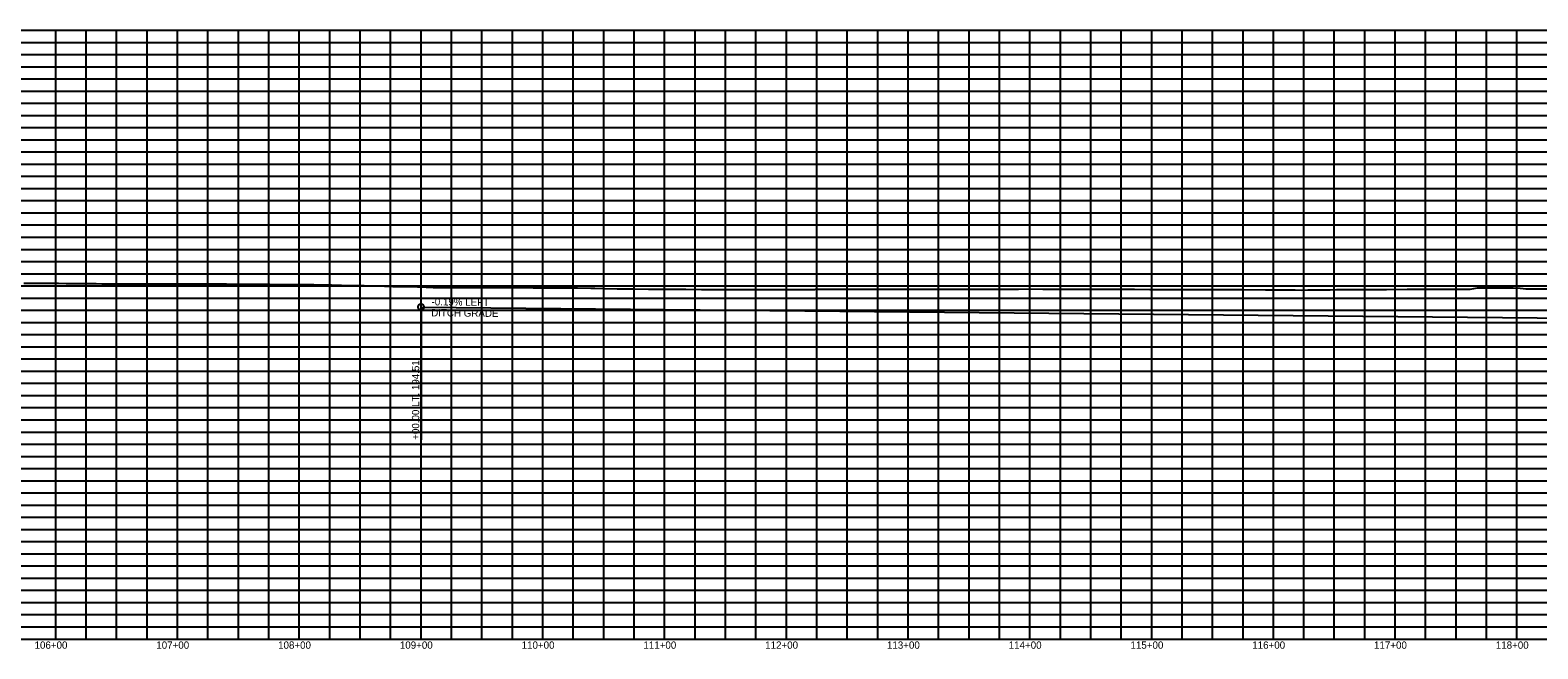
# Model space of a CAD drawing. Extents: x 1399671 to 1408349, y 1930471 to 1933387.
# Drawn here: x 1400903 to 1402141, y 1932871 to 1933379 of the extents above; entities that cross this region are included whole.
import ezdxf

# ---------------------------------------------------------------- set-up
doc = ezdxf.new("R2010")
doc.units = 0
for name, color, linetype in [('R_Exist Surface', 7, 'Continuous'), ('R_Grid', 7, 'Continuous'), ('R_Grid Annot', 7, 'Continuous'), ('R_Vert Alg', 7, 'Continuous'), ('R_Vert Alg Annot', 7, 'Continuous')]:
    doc.layers.add(name, color=color, linetype=linetype)

msp = doc.modelspace()

# ---------------------------------------------------------------- linework, layer by layer
at = {"layer": 'R_Exist Surface'}
msp.add_lwpolyline([(1400897.9, 1933170.9), (1400905.4, 1933170.8), (1400912.1, 1933170.8), (1400918.2, 1933170.7), (1400919.1, 1933170.7), (1400926.4, 1933170.7), (1400932.8, 1933170.6), (1400940.1, 1933170.6), (1400947.4, 1933170.5), (1400957.3, 1933170.5), (1400962, 1933170.4), (1400974.2, 1933170.3), (1400981.9, 1933170.3), (1400983.9, 1933170.3), (1401000.9, 1933170.3), (1401005.8, 1933170.3), (1401006.3, 1933170.3), (1401027.6, 1933170.3), (1401027.6, 1933170.3), (1401030.7, 1933170.3), (1401042.9, 1933170.2), (1401043.8, 1933170.2), (1401049.5, 1933170.2), (1401056.6, 1933170.2), (1401057, 1933170.2), (1401064.4, 1933170.2), (1401070.1, 1933170.1), (1401070.8, 1933170.1), (1401071.2, 1933170.1), (1401083.2, 1933169.9), (1401085.4, 1933169.9), (1401092.8, 1933169.9), (1401096.3, 1933169.9), (1401100.1, 1933169.9), (1401109.5, 1933169.8), (1401114.5, 1933169.8), (1401114.7, 1933169.8), (1401122.6, 1933169.8), (1401129.3, 1933169.8), (1401135.8, 1933169.7), (1401136.1, 1933169.7), (1401150.7, 1933169.4), (1401157.8, 1933169.2), (1401159, 1933169.2), (1401177.6, 1933168.8), (1401179.4, 1933168.7), (1401182.3, 1933168.7), (1401194.3, 1933168.4), (1401195.3, 1933168.4), (1401201, 1933168.2), (1401205.4, 1933168.2), (1401208.4, 1933168.1), (1401208.4, 1933168.1), (1401221.3, 1933167.8), (1401221.6, 1933167.7), (1401222.7, 1933167.7), (1401234.2, 1933167.4), (1401234.7, 1933167.4), (1401244.3, 1933167.4), (1401247.3, 1933167.4), (1401248, 1933167.4), (1401260.5, 1933167.3), (1401261.3, 1933167.3), (1401262.1, 1933167.3), (1401266, 1933167.3), (1401274.5, 1933167.3), (1401275.5, 1933167.3), (1401287.6, 1933167.2), (1401287.8, 1933167.2), (1401289, 1933167.2), (1401301.4, 1933167.2), (1401302.7, 1933167.2), (1401309.3, 1933167.2), (1401314.9, 1933167.2), (1401316.4, 1933167.1), (1401328.5, 1933167.1), (1401330.1, 1933167.1), (1401330.9, 1933167.1), (1401342, 1933167.1), (1401344.9, 1933167.1), (1401352.6, 1933166.9), (1401363.6, 1933166.7), (1401366.8, 1933166.7), (1401374.2, 1933166.5), (1401385.3, 1933166.3), (1401395.8, 1933166.2), (1401397.1, 1933166.2), (1401399.4, 1933166.2), (1401411.1, 1933166), (1401413.5, 1933166), (1401417.5, 1933166), (1401425.1, 1933165.9), (1401427.6, 1933165.9), (1401439.1, 1933165.8), (1401439.1, 1933165.8), (1401441.7, 1933165.8), (1401454.4, 1933165.7), (1401457.3, 1933165.7), (1401460.8, 1933165.7), (1401470, 1933165.6), (1401472.9, 1933165.6), (1401475.8, 1933165.7), (1401482.4, 1933165.6), (1401488.5, 1933165.6), (1401491.4, 1933165.6), (1401504.1, 1933165.5), (1401504.1, 1933165.5), (1401506.8, 1933165.6), (1401517.7, 1933165.6), (1401520.5, 1933165.6), (1401525.7, 1933165.6), (1401531.4, 1933165.6), (1401534.3, 1933165.7), (1401545.1, 1933165.7), (1401547.4, 1933165.7), (1401548, 1933165.8), (1401558.8, 1933165.8), (1401562, 1933165.8), (1401569, 1933165.8), (1401573.2, 1933165.8), (1401576.5, 1933165.8), (1401587.7, 1933165.9), (1401590.6, 1933165.9), (1401598.8, 1933166), (1401602.1, 1933166), (1401613.1, 1933166), (1401616.5, 1933166), (1401627.6, 1933166), (1401630.7, 1933166), (1401641.9, 1933166), (1401645, 1933166), (1401656.1, 1933166), (1401659.2, 1933165.9), (1401670.4, 1933165.9), (1401673.4, 1933165.9), (1401676.3, 1933165.9), (1401686.2, 1933165.9), (1401689.1, 1933166), (1401699, 1933166), (1401702, 1933166), (1401711.8, 1933166), (1401714.9, 1933166), (1401724.7, 1933166.1), (1401734.8, 1933166), (1401738, 1933166), (1401748.2, 1933166), (1401751.4, 1933166), (1401761.5, 1933166), (1401764.7, 1933166), (1401774.9, 1933165.9), (1401778.1, 1933165.9), (1401790.5, 1933165.9), (1401794.1, 1933165.9), (1401806.5, 1933165.8), (1401810.1, 1933165.8), (1401822.6, 1933165.7), (1401826.1, 1933165.7), (1401829.6, 1933165.7), (1401842.2, 1933165.6), (1401845.3, 1933165.6), (1401856.3, 1933165.6), (1401859.5, 1933165.6), (1401870.5, 1933165.6), (1401873.6, 1933165.5), (1401884.6, 1933165.5), (1401895.6, 1933165.5), (1401898.8, 1933165.5), (1401917.7, 1933165.4), (1401923, 1933165.4), (1401941.9, 1933165.3), (1401947.2, 1933165.2), (1401952.4, 1933165.4), (1401970.9, 1933165.4), (1401976.1, 1933165.5), (1401994.7, 1933165.6), (1401997.4, 1933165.5), (1402014.3, 1933165.7), (1402017.1, 1933165.7), (1402034.1, 1933165.9), (1402036.8, 1933165.8), (1402039.4, 1933165.8), (1402052.7, 1933165.9), (1402056.8, 1933165.8), (1402070.4, 1933165.9), (1402076.9, 1933165.9), (1402085.8, 1933166), (1402091.7, 1933167.1), (1402104.4, 1933167.1), (1402121.1, 1933167.1), (1402126.8, 1933166.8), (1402129.2, 1933166.5), (1402131.6, 1933166.2), (1402150.7, 1933166.1)], dxfattribs=at)
at = {"layer": 'R_Grid'}
for p, q in [((1400324.2, 1933378.6), (1408224.2, 1933378.6)), ((1400324.2, 1933378.6), (1408224.2, 1933378.6)), ((1400324.2, 1933368.6), (1408224.2, 1933368.6)), ((1400924.2, 1932878.6), (1400924.2, 1933378.6)), ((1400949.2, 1932878.6), (1400949.2, 1933378.6)), ((1400974.2, 1932878.6), (1400974.2, 1933378.6)), ((1400999.2, 1932878.6), (1400999.2, 1933378.6)), ((1401024.2, 1932878.6), (1401024.2, 1933378.6)), ((1401049.2, 1932878.6), (1401049.2, 1933378.6)), ((1401074.2, 1932878.6), (1401074.2, 1933378.6)), ((1401099.2, 1932878.6), (1401099.2, 1933378.6)), ((1401124.2, 1932878.6), (1401124.2, 1933378.6)), ((1401149.2, 1932878.6), (1401149.2, 1933378.6)), ((1401174.2, 1932878.6), (1401174.2, 1933378.6)), ((1401199.2, 1932878.6), (1401199.2, 1933378.6)), ((1401224.2, 1932878.6), (1401224.2, 1933378.6)), ((1401249.2, 1932878.6), (1401249.2, 1933378.6)), ((1401274.2, 1932878.6), (1401274.2, 1933378.6)), ((1401299.2, 1932878.6), (1401299.2, 1933378.6)), ((1401324.2, 1932878.6), (1401324.2, 1933378.6)), ((1401349.2, 1932878.6), (1401349.2, 1933378.6)), ((1401374.2, 1932878.6), (1401374.2, 1933378.6)), ((1401399.2, 1932878.6), (1401399.2, 1933378.6)), ((1401424.2, 1932878.6), (1401424.2, 1933378.6)), ((1401449.2, 1932878.6), (1401449.2, 1933378.6)), ((1401474.2, 1932878.6), (1401474.2, 1933378.6)), ((1401499.2, 1932878.6), (1401499.2, 1933378.6)), ((1401524.2, 1932878.6), (1401524.2, 1933378.6)), ((1401549.2, 1932878.6), (1401549.2, 1933378.6)), ((1401574.2, 1932878.6), (1401574.2, 1933378.6)), ((1401599.2, 1932878.6), (1401599.2, 1933378.6)), ((1401624.2, 1932878.6), (1401624.2, 1933378.6)), ((1401649.2, 1932878.6), (1401649.2, 1933378.6)), ((1401674.2, 1932878.6), (1401674.2, 1933378.6)), ((1401699.2, 1932878.6), (1401699.2, 1933378.6)), ((1401724.2, 1932878.6), (1401724.2, 1933378.6)), ((1401749.2, 1932878.6), (1401749.2, 1933378.6)), ((1401774.2, 1932878.6), (1401774.2, 1933378.6)), ((1401799.2, 1932878.6), (1401799.2, 1933378.6)), ((1401824.2, 1932878.6), (1401824.2, 1933378.6)), ((1401849.2, 1932878.6), (1401849.2, 1933378.6)), ((1401874.2, 1932878.6), (1401874.2, 1933378.6)), ((1401899.2, 1932878.6), (1401899.2, 1933378.6)), ((1401924.2, 1932878.6), (1401924.2, 1933378.6)), ((1401949.2, 1932878.6), (1401949.2, 1933378.6)), ((1401974.2, 1932878.6), (1401974.2, 1933378.6)), ((1401999.2, 1932878.6), (1401999.2, 1933378.6)), ((1402024.2, 1932878.6), (1402024.2, 1933378.6)), ((1402049.2, 1932878.6), (1402049.2, 1933378.6)), ((1402074.2, 1932878.6), (1402074.2, 1933378.6)), ((1402099.2, 1932878.6), (1402099.2, 1933378.6)), ((1402124.2, 1932878.6), (1402124.2, 1933378.6)), ((1400324.2, 1933358.6), (1408224.2, 1933358.6)), ((1400324.2, 1933348.6), (1408224.2, 1933348.6)), ((1400324.2, 1933338.6), (1408224.2, 1933338.6)), ((1400324.2, 1933328.6), (1408224.2, 1933328.6)), ((1400324.2, 1933318.6), (1408224.2, 1933318.6)), ((1400324.2, 1933308.6), (1408224.2, 1933308.6)), ((1400324.2, 1933298.6), (1408224.2, 1933298.6)), ((1400324.2, 1933288.6), (1408224.2, 1933288.6)), ((1400324.2, 1933278.6), (1408224.2, 1933278.6)), ((1400324.2, 1933268.6), (1408224.2, 1933268.6)), ((1400324.2, 1933258.6), (1408224.2, 1933258.6)), ((1400324.2, 1933248.6), (1408224.2, 1933248.6)), ((1400324.2, 1933238.6), (1408224.2, 1933238.6)), ((1400324.2, 1933228.6), (1408224.2, 1933228.6)), ((1400324.2, 1933218.6), (1408224.2, 1933218.6)), ((1400324.2, 1933208.6), (1408224.2, 1933208.6)), ((1400324.2, 1933198.6), (1408224.2, 1933198.6)), ((1400324.2, 1933188.6), (1408224.2, 1933188.6)), ((1400324.2, 1933178.6), (1408224.2, 1933178.6)), ((1400324.2, 1933168.6), (1408224.2, 1933168.6)), ((1400324.2, 1933158.6), (1408224.2, 1933158.6)), ((1400324.2, 1933148.6), (1408224.2, 1933148.6)), ((1400324.2, 1933138.6), (1408224.2, 1933138.6)), ((1400324.2, 1933128.6), (1408224.2, 1933128.6)), ((1400324.2, 1933118.6), (1408224.2, 1933118.6)), ((1400324.2, 1933108.6), (1408224.2, 1933108.6)), ((1400324.2, 1933098.6), (1408224.2, 1933098.6)), ((1400324.2, 1933088.6), (1408224.2, 1933088.6)), ((1400324.2, 1933078.6), (1408224.2, 1933078.6)), ((1400324.2, 1933068.6), (1408224.2, 1933068.6)), ((1400324.2, 1933058.6), (1408224.2, 1933058.6)), ((1400324.2, 1933048.6), (1408224.2, 1933048.6)), ((1400324.2, 1933038.6), (1408224.2, 1933038.6)), ((1400324.2, 1933028.6), (1408224.2, 1933028.6)), ((1400324.2, 1933018.6), (1408224.2, 1933018.6)), ((1400324.2, 1933008.6), (1408224.2, 1933008.6)), ((1400324.2, 1932998.6), (1408224.2, 1932998.6)), ((1400324.2, 1932988.6), (1408224.2, 1932988.6)), ((1400324.2, 1932978.6), (1408224.2, 1932978.6)), ((1400324.2, 1932968.6), (1408224.2, 1932968.6)), ((1400324.2, 1932958.6), (1408224.2, 1932958.6)), ((1400324.2, 1932948.6), (1408224.2, 1932948.6)), ((1400324.2, 1932938.6), (1408224.2, 1932938.6)), ((1400324.2, 1932928.6), (1408224.2, 1932928.6)), ((1400324.2, 1932918.6), (1408224.2, 1932918.6)), ((1400324.2, 1932908.6), (1408224.2, 1932908.6)), ((1400324.2, 1932898.6), (1408224.2, 1932898.6)), ((1400324.2, 1932888.6), (1408224.2, 1932888.6)), ((1400324.2, 1932878.6), (1408224.2, 1932878.6))]:
    msp.add_line(p, q, dxfattribs=at)
at = {"layer": 'R_Vert Alg'}
msp.add_line((1401224.2, 1933151.2), (1403622.2, 1933128.4), dxfattribs=at)
at = {"layer": 'R_Vert Alg Annot'}
for p, q in [((1401224.2, 1933151.2), (1401224.2, 1933126.2)), ((1401224.2, 1933126.2), (1401224.2, 1933042.2))]:
    msp.add_line(p, q, dxfattribs=at)
msp.add_circle((1401224.2, 1933151.2), 2.5, dxfattribs=at)

# ---------------------------------------------------------------- texts
at = {"layer": 'R_Grid Annot'}
for s, p in [('106+00', (1400906.8, 1932870.6)), ('107+00', (1401006.8, 1932870.6)), ('108+00', (1401106.8, 1932870.6)), ('109+00', (1401206.8, 1932870.6)), ('110+00', (1401306.8, 1932870.6)), ('111+00', (1401406.8, 1932870.6)), ('112+00', (1401506.8, 1932870.6)), ('113+00', (1401606.8, 1932870.6)), ('114+00', (1401706.8, 1932870.6)), ('115+00', (1401806.8, 1932870.6)), ('116+00', (1401906.8, 1932870.6)), ('117+00', (1402006.8, 1932870.6)), ('118+00', (1402106.8, 1932870.6))]:
    msp.add_text(s, height=6, dxfattribs=at).set_placement(p)
at = {"layer": 'R_Vert Alg Annot'}
for s, rotation, p in [('-0.19% LEFT', 359.4553, (1401232.8, 1933152.6)), ('DITCH GRADE', 359.4553, (1401232.5, 1933143.6)), ('+00.00 LT. 194.51', 90, (1401222.7, 1933042.2))]:
    msp.add_text(s, height=6, rotation=rotation, dxfattribs=at).set_placement(p)

doc.saveas('drawing.dxf')
